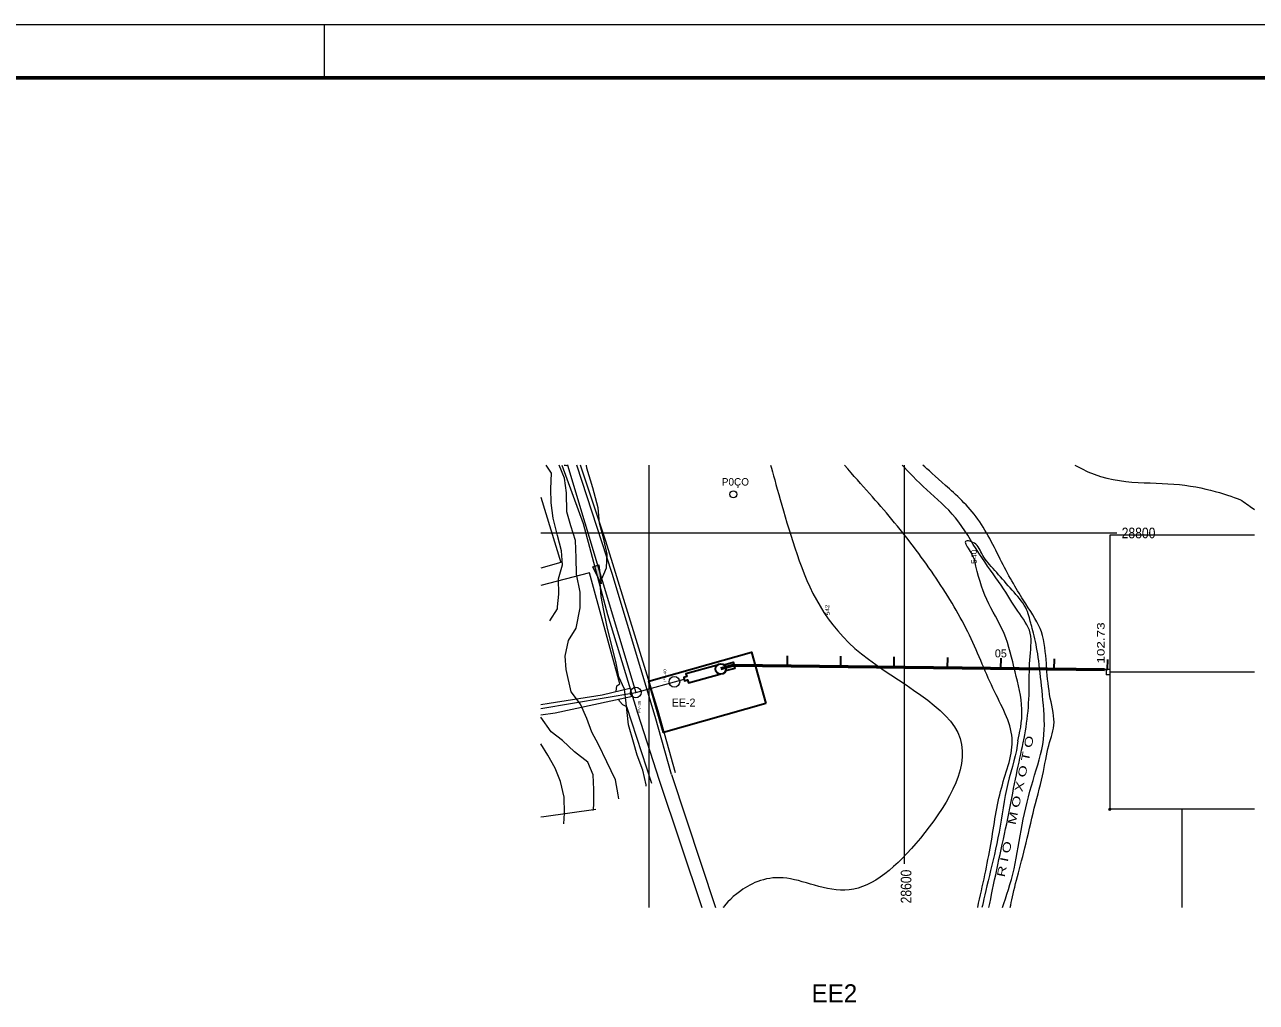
# Model space of a CAD drawing. Extents: x 949 to 2631, y -1701 to -513.
# Drawn here: x 1448.6 to 1910.3, y -879.3 to -512.7 of the extents above; entities that cross this region are included whole.
import ezdxf
from ezdxf.enums import TextEntityAlignment as Align

# ---------------------------------------------------------------- set-up
doc = ezdxf.new("R2010")
doc.units = 0
doc.header["$LTSCALE"] = 1.2
doc.header["$PDMODE"] = 32
doc.header["$PDSIZE"] = 0.6
for name, color, linetype, lineweight in [('10', 7, 'Continuous', 13), ('11', 7, 'Continuous', 13), ('13', 7, 'Continuous', 35), ('15', 7, 'Continuous', 35), ('2', 7, 'Continuous', 13), ('20', 7, 'Continuous', 13), ('21', 7, 'Continuous', 13), ('3', 7, 'Continuous', 13), ('32', 7, 'Continuous', 13), ('33', 7, 'Continuous', 25), ('34', 7, 'Continuous', 35), ('4', 7, 'Continuous', 13), ('5', 7, 'Continuous', 13), ('6', 7, 'Continuous', 60), ('7', 7, 'Continuous', 35)]:
    doc.layers.add(name, color=color, linetype=linetype, lineweight=lineweight)
doc.layers.add('12', color=7, linetype='Continuous')

msp = doc.modelspace()

# ---------------------------------------------------------------- hatches: boundary and pattern name
at = {"layer": '33'}
msp.add_hatch(color=256, dxfattribs=at).paths.add_polyline_path([(1664.692, -722.375), (1661.53, -716.015), (1663.829, -715.326)])

# ---------------------------------------------------------------- linework, layer by layer
at = {"layer": '10'}
for points in [[(1692.552, -793.222), (1686.032, -770.012), (1666.392, -706.372), (1656.944, -677.861)], [(1642.05, -689.86), (1649.512, -714.342), (1642.05, -716.511)], [(1670.362, -762.732), (1670.612, -760.692), (1671.732, -759.952), (1660.302, -718.282), (1642.05, -722.988)], [(1683.742, -797.252), (1674.272, -768.552), (1672.852, -767.802), (1671.552, -766.432), (1671.312, -765.702)], [(1642.05, -809.81), (1643.152, -809.662), (1662.662, -806.912)]]:
    msp.add_lwpolyline(points, dxfattribs=at)
at = {"layer": '12'}
msp.add_point((1855.336, -806.933), dxfattribs=at)
at = {"layer": '13'}
msp.add_lwpolyline([(1726.415, -767.277), (1688.04, -778.095), (1682.496, -758.84), (1721.006, -748.022)], close=True, dxfattribs=at)
at = {"layer": '15'}
msp.add_lwpolyline([(1708.271, -752.84), (1696.445, -756.121), (1696.744, -757.199), (1695.636, -757.507), (1695.984, -758.759), (1697.092, -758.452), (1697.394, -759.542), (1709.22, -756.261)], dxfattribs=at)
msp.add_circle((1709.524, -754.335), 1.95, dxfattribs=at)
at = {"layer": '2'}
for p, q in [((1778.222, -677.861), (1778.222, -827.369)), ((1909.635, -755.568), (1855.336, -755.568))]:
    msp.add_line(p, q, dxfattribs=at)
at = {"layer": '20'}
for points in [[(1649.992, -677.861), (1657.882, -699.742), (1667.012, -733.932), (1678.252, -770.722), (1686.492, -796.002)], [(1691.042, -793.912), (1684.962, -772.162), (1668.762, -718.582), (1655.594, -677.861)], [(1642.05, -767.688), (1645.162, -767.192), (1665.072, -764.052), (1675.422, -761.462)], [(1676.382, -764.612), (1647.422, -770.872), (1642.05, -771.66)]]:
    msp.add_lwpolyline(points, dxfattribs=at)
at = {"layer": '21'}
for p, q in [((1682.632, -843.783), (1682.632, -677.861)), ((1642.05, -703.242), (1857.948, -703.242))]:
    msp.add_line(p, q, dxfattribs=at)
at = {"layer": '3'}
for p, q in [((1691.042, -793.912), (1707.547, -843.783)), ((1686.492, -796.002), (1702.372, -843.783))]:
    msp.add_line(p, q, dxfattribs=at)
at = {"layer": '3', "lineweight": 35}
msp.add_lwpolyline([(1710.684, -752.768), (1714.214, -751.789), (1714.855, -754.101), (1711.326, -755.08)], dxfattribs=at)
at = {"layer": '32'}
for p in [(1652.086, -677.861), (1642.05, -769.171)]:
    msp.add_line(p, (1677.687, -763.161), dxfattribs=at)
at = {"layer": '33', "lineweight": 13}
msp.add_lwpolyline([(1664.692, -722.375), (1661.53, -716.015), (1663.829, -715.326)], close=True, dxfattribs=at)
msp.add_circle((1677.687, -763.161), 2, dxfattribs=at)
msp.add_arc((1651.527, -676.001), 2, 248.44274, 291.55726, dxfattribs=at)
at = {"layer": '34'}
for p, q in [((1734.533, -753.179), (1734.578, -749.35)), ((1754.532, -753.413), (1754.577, -749.584)), ((1774.53, -753.647), (1774.575, -749.818)), ((1794.529, -753.88), (1794.574, -750.052)), ((1814.528, -754.114), (1814.572, -750.286)), ((1834.526, -754.348), (1834.571, -750.52)), ((1854.525, -754.582), (1854.57, -750.753)), ((1714.534, -752.945), (1854.525, -754.582))]:
    msp.add_line(p, q, dxfattribs=at)
at = {"layer": '34', "lineweight": 53}
for q in [(1709.524, -754.335), (1853.336, -754.568)]:
    msp.add_line((1714.534, -752.945), q, dxfattribs=at)
at = {"layer": '4'}
for p, q in [((1855.336, -704.203), (1855.336, -806.933)), ((1909.635, -704.203), (1855.336, -704.203)), ((1853.997, -754.568), (1853.997, -756.568)), ((1855.336, -754.568), (1853.997, -754.568)), ((1855.336, -756.568), (1853.997, -756.568)), ((1909.635, -806.933), (1855.336, -806.933)), ((1882.336, -806.933), (1855.336, -806.933)), ((1882.336, -806.933), (1882.336, -843.783))]:
    msp.add_line(p, q, dxfattribs=at)
for points in [[(1645.492, -736.232), (1648.322, -731.802), (1648.382, -731.002), (1648.382, -730.972), (1648.762, -726.242), (1648.662, -720.552), (1650.252, -715.272), (1649.802, -710.072), (1648.272, -704.322), (1646.702, -697.792), (1645.892, -692.082), (1645.872, -686.772), (1646.012, -680.902), (1644.076, -677.861)], [(1661.732, -807.342), (1661.902, -805.462), (1661.912, -799.522), (1661.692, -793.962), (1659.702, -789.242), (1654.732, -785.352), (1650.172, -781.142), (1645.942, -777.892), (1642.05, -772.432)]]:
    msp.add_lwpolyline(points, dxfattribs=at)
at = {"layer": '5'}
for p, q in [((948.926, -512.728), (2630.926, -512.728)), ((1560.926, -532.728), (1560.926, -512.728))]:
    msp.add_line(p, q, dxfattribs=at)
for points in [[(1671.272, -802.972), (1671.092, -801.542), (1670.002, -795.932), (1666.802, -789.092), (1663.742, -782.612), (1661.252, -777.962), (1659.292, -772.882), (1656.952, -767.552), (1653.462, -762.902), (1651.512, -754.462), (1651.232, -749.462), (1652.462, -743.672), (1655.272, -739.082), (1656.762, -731.352), (1656.822, -725.562), (1655.402, -718.722), (1655.332, -712.672), (1655.062, -706.122), (1653.302, -700.632), (1651.862, -695.452), (1651.662, -688.312), (1650.932, -682.772), (1648.958, -677.861)], [(1681.592, -798.242), (1681.512, -797.812), (1680.312, -792.272), (1678.182, -786.702), (1676.782, -781.752), (1674.932, -775.222), (1674.122, -767.112), (1673.392, -761.952), (1671.322, -757.232), (1670.212, -751.542), (1668.712, -745.702), (1666.882, -738.502), (1665.722, -732.432), (1664.682, -727.172), (1664.272, -722.072), (1666.632, -716.362), (1666.942, -711.282), (1665.522, -705.162), (1664.072, -699.622), (1663.572, -693.882), (1661.512, -686.462), (1659.352, -679.032), (1659.172, -677.861)], [(1650.682, -812.412), (1650.932, -808.442), (1650.862, -802.362), (1649.392, -796.552), (1647.432, -791.572), (1644.732, -786.622), (1642.05, -782.426)]]:
    msp.add_lwpolyline(points, dxfattribs=at)
msp.add_circle((1714.254, -688.833), 1.32, dxfattribs=at)
for points in [[(1728.22, -677.861), (1729.912, -683.907), (1736.106, -708.224), (1752.473, -749), (1812.912, -775.338), (1785.953, -818.765), (1759.305, -843.329), (1732.847, -829.043), (1715.242, -837.29), (1710.488, -843.591), (1710.348, -843.783)], [(1805.825, -843.783), (1807.754, -835.158), (1811.098, -819.862), (1813.853, -798.434), (1821.851, -780.192), (1811.117, -762.181), (1802.866, -740.236), (1789.939, -719.009), (1773.725, -697.713), (1762.704, -685.706), (1755.869, -677.861)], [(1818.023, -843.783), (1818.494, -841.528), (1819.847, -835.061), (1823.096, -823.753), (1826.497, -808.167), (1830.465, -793.925), (1832.197, -782.325), (1835.49, -774.83), (1832.412, -763.911), (1831.583, -752.533), (1830.643, -739.794), (1824.3, -731.006), (1815.26, -715.849), (1806.799, -697.11), (1793.026, -684.831), (1786.995, -679.421), (1785.27, -677.861)], [(1842.282, -677.861), (1855.146, -685.658), (1880.594, -682.486), (1900.838, -689.342), (1904.849, -691.139)], [(1904.849, -691.139), (1906.548, -692.415), (1908.153, -693.557), (1909.635, -694.528)], [(1825.606, -736.782), (1825.392, -735.783), (1824.364, -730.963), (1818.78, -724.928), (1812.871, -717.931), (1807.558, -712.433), (1805.923, -706.868), (1799.587, -705.555), (1803.322, -710.278), (1804.516, -713.188), (1804.721, -713.818)], [(1820.856, -781.228), (1821.541, -778.767), (1823.515, -769.366), (1819.803, -755.573), (1816.437, -740.436), (1808.565, -728.66), (1805.946, -719.298), (1804.721, -713.818)], [(1815.18, -843.783), (1816.455, -839.735), (1820.004, -829.469), (1822.092, -812.775), (1826.446, -795.789), (1831.523, -780.815), (1830.309, -765.848), (1828.88, -751.914), (1827.385, -742.763), (1825.87, -737.606), (1825.606, -736.782)], [(1820.856, -781.228), (1820.527, -785.992), (1816.471, -796.775), (1814.12, -815.993), (1810.105, -831.995), (1807.794, -841.977), (1807.385, -843.783)]]:
    msp.add_open_spline(points, degree=3, dxfattribs=at)
at = {"layer": '6'}
msp.add_line((998.926, -532.728), (2610.926, -532.728), dxfattribs=at)
at = {"layer": '6', "lineweight": 13}
msp.add_line((1677.687, -763.161), (1695.81, -758.133), dxfattribs=at)
at = {"layer": '7', "lineweight": 13}
msp.add_circle((1692.133, -759.153), 2, dxfattribs=at)
msp.add_open_spline([(1810.06, -843.783), (1810.887, -839.712), (1812.888, -829.608), (1816.389, -814.452), (1819.354, -798.492), (1822.022, -786.083), (1824.421, -774.777), (1825.309, -762.64), (1824.998, -750.789), (1826.822, -740.436), (1820.778, -732.971), (1815.218, -723.246), (1806.077, -711.408), (1798.167, -696.862), (1786.416, -687.324), (1779.804, -680.298), (1777.461, -677.861)], degree=3, dxfattribs=at)

# ---------------------------------------------------------------- texts
at = {"layer": '10'}
msp.add_text('EE2', height=6.772, dxfattribs=at).set_placement((1743.539, -879.333))
at = {"layer": '11', "width": 1.25}
for s, p in [('PV-40', (1689.067, -759.08)), ('PV-39', (1679.468, -770.846))]:
    msp.add_text(s, height=1, rotation=90, dxfattribs=at).set_placement(p)
at = {"layer": '21', "width": 0.85}
msp.add_text('28800', height=4, dxfattribs=at).set_placement((1859.794, -705.329))
msp.add_text('28600', height=4, rotation=90, dxfattribs=at).set_placement((1780.974, -842.217))
at = {"layer": '34'}
for s, p in [('05', (1814.496, -749.978)), ('EE-2', (1695.582, -768.424))]:
    msp.add_text(s, height=3, dxfattribs=at).set_placement(p, align=Align.CENTER)
at = {"layer": '5'}
msp.add_text('P0ÇO', height=2.8, dxfattribs=at).set_placement((1709.911, -685.56))
for s, height, rotation, width, p in [('540', 2, 90.066, 1.2, (1805.437, -714.923)), ('542', 1.5, 94.394, 1.2, (1750.44, -734.153)), ('102.73', 2.8, 90, 1.35, (1853.385, -752.303)), ('R I O    M O X O T Ó', 3, 78.217, 1.45, (1815.893, -832.551))]:
    msp.add_text(s, height=height, rotation=rotation, dxfattribs=dict(at, width=width)).set_placement(p)

doc.saveas('drawing.dxf')
